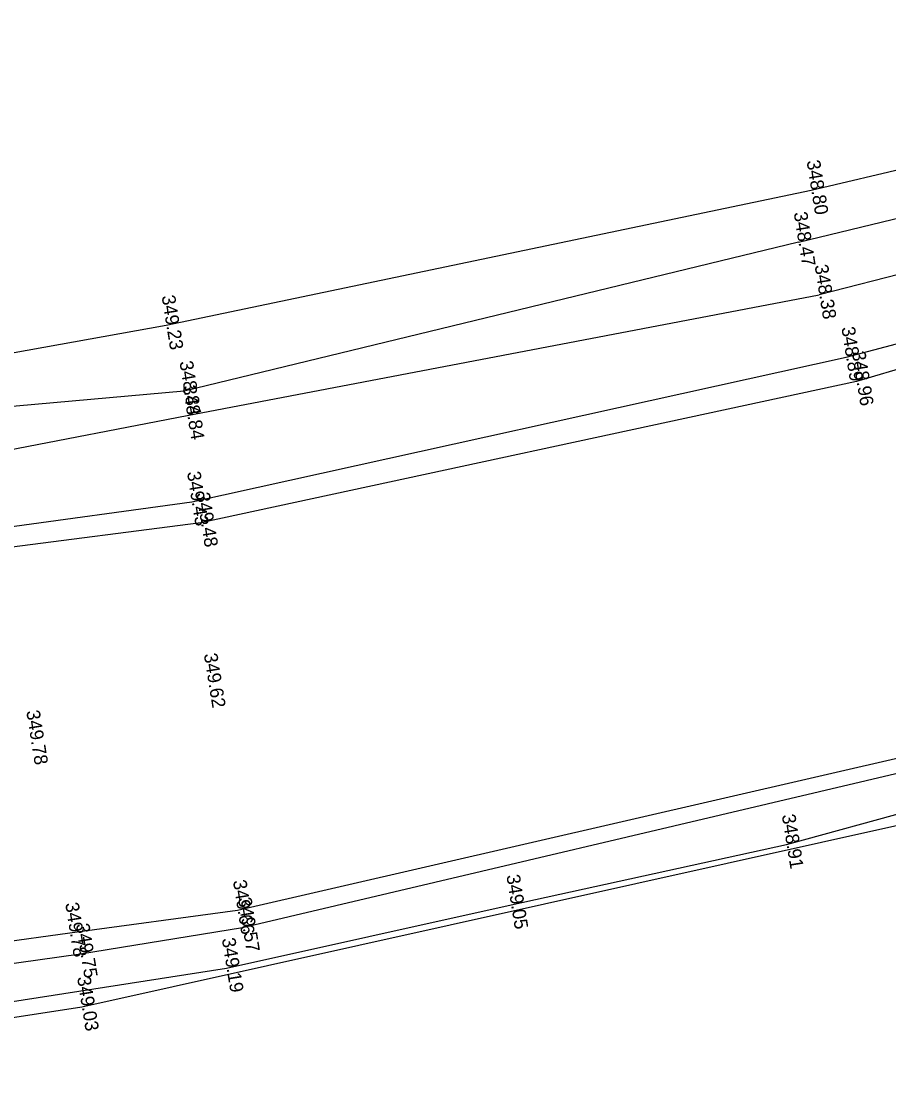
# Model space of a CAD drawing. Extents: x -600096 to -597522, y -1151695 to -1149849.
# Drawn here: x -599542.24 to -599530.19, y -1151594.88 to -1151580.19 of the extents above; entities that cross this region are included whole.
import ezdxf

# ---------------------------------------------------------------- set-up
doc = ezdxf.new("R2010")
doc.units = 0
for name, color, linetype in [('Hrana komunikace', 7, 'Continuous'), ('MPPV_Dno_prikopu', 7, 'Continuous'), ('MPPV_komunikace', 7, 'Continuous'), ('MPPV_svah', 7, 'Continuous'), ('Svodidla', 7, 'Continuous'), ('Vrstva 12', 7, 'Continuous')]:
    doc.layers.add(name, color=color, linetype=linetype)

msp = doc.modelspace()

# ---------------------------------------------------------------- linework, layer by layer
at = {"layer": 'Hrana komunikace'}
for p, q in [((-599530.786, -1151584.848), (-599520.851, -1151582.258)), ((-599539.872, -1151586.856), (-599530.786, -1151584.848)), ((-599542.577, -1151587.23), (-599539.872, -1151586.856)), ((-599539.165, -1151592.769), (-599529.035, -1151590.381)), ((-599541.416, -1151593.13), (-599539.165, -1151592.769)), ((-599547.999, -1151594.077), (-599541.416, -1151593.13))]:
    msp.add_line(p, q, dxfattribs=at)
at = {"layer": 'MPPV_Dno_prikopu'}
for p, q in [((-599531.447, -1151583.253), (-599521.589, -1151580.878)), ((-599521.315, -1151581.452), (-599531.157, -1151583.986)), ((-599531.447, -1151583.253), (-599539.977, -1151585.323)), ((-599539.933, -1151585.66), (-599531.157, -1151583.986)), ((-599539.977, -1151585.323), (-599542.773, -1151585.57)), ((-599542.851, -1151586.221), (-599539.933, -1151585.66))]:
    msp.add_line(p, q, dxfattribs=at)
at = {"layer": 'MPPV_komunikace'}
for p, q in [((-599520.851, -1151582.258), (-599530.64, -1151585.189)), ((-599530.64, -1151585.189), (-599539.744, -1151587.149)), ((-599539.744, -1151587.149), (-599542.552, -1151587.51)), ((-599539.234, -1151592.527), (-599529.087, -1151590.186)), ((-599541.564, -1151592.84), (-599539.234, -1151592.527)), ((-599548.022, -1151593.747), (-599541.564, -1151592.84))]:
    msp.add_line(p, q, dxfattribs=at)
at = {"layer": 'MPPV_svah'}
for p, q in [((-599521.316, -1151580.186), (-599531.269, -1151582.536)), ((-599531.269, -1151582.536), (-599540.225, -1151584.411)), ((-599540.225, -1151584.411), (-599542.971, -1151584.903)), ((-599541.399, -1151593.867), (-599528.931, -1151591.093)), ((-599548.022, -1151594.881), (-599541.399, -1151593.867))]:
    msp.add_line(p, q, dxfattribs=at)
at = {"layer": 'Svodidla'}
for p, q in [((-599531.612, -1151591.615), (-599527.673, -1151590.536)), ((-599535.438, -1151592.453), (-599531.612, -1151591.615)), ((-599539.388, -1151593.331), (-599535.438, -1151592.453)), ((-599543.262, -1151593.934), (-599539.388, -1151593.331))]:
    msp.add_line(p, q, dxfattribs=at)

# ---------------------------------------------------------------- texts
at = {"layer": 'Vrstva 12'}
for s, p in [('348.80 ', (-599531.334, -1151582.128)), ('348.47 ', (-599531.513, -1151582.845)), ('348.38 ', (-599531.223, -1151583.578)), ('349.23 ', (-599540.29, -1151584.003)), ('348.89 ', (-599530.851, -1151584.44)), ('348.96 ', (-599530.705, -1151584.781)), ('348.84 ', (-599540.042, -1151584.915)), ('348.84 ', (-599539.998, -1151585.252)), ('349.43 ', (-599539.938, -1151586.448)), ('349.48 ', (-599539.809, -1151586.741)), ('349.62 ', (-599539.704, -1151588.973)), ('349.78 ', (-599542.17, -1151589.764)), ('348.91 ', (-599531.678, -1151591.207)), ('349.05 ', (-599535.503, -1151592.045)), ('349.66 ', (-599539.3, -1151592.119)), ('349.57 ', (-599539.23, -1151592.361)), ('349.78 ', (-599541.629, -1151592.432)), ('349.75 ', (-599541.481, -1151592.723)), ('349.19 ', (-599539.454, -1151592.923)), ('349.03 ', (-599541.464, -1151593.459))]:
    msp.add_text(s, height=0.1875, rotation=279.1328, dxfattribs=at).set_placement(p)

doc.saveas('drawing.dxf')
